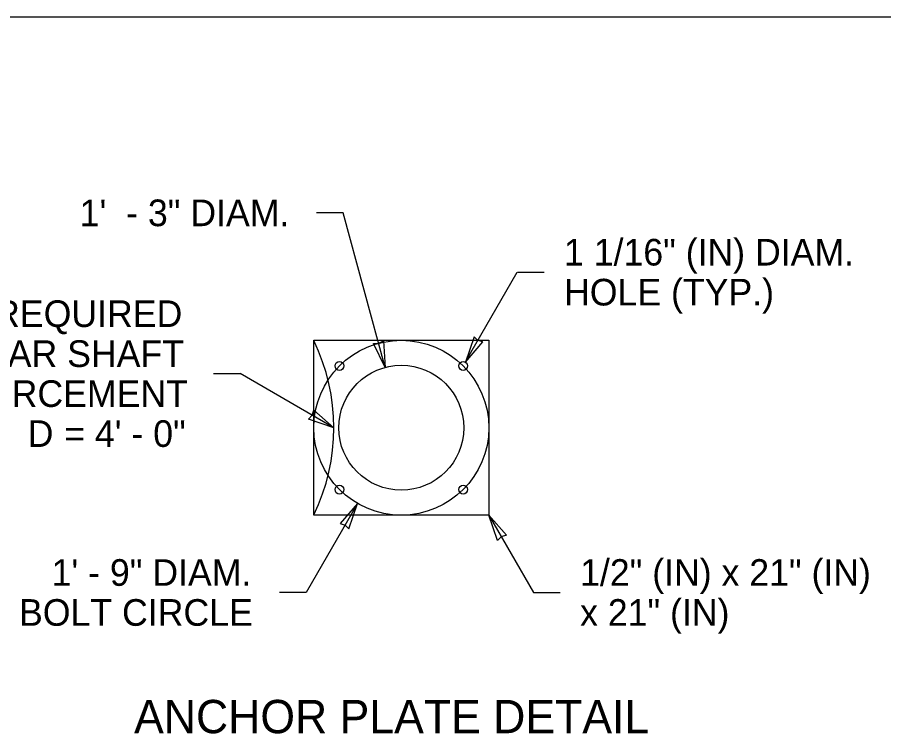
# Model space of a CAD drawing. Extents: x 99862 to 103151, y 100000 to 102076.
# Drawn here: x 102253 to 102772, y 101645 to 102075 of the extents above; entities that cross this region are included whole.
import ezdxf

# ---------------------------------------------------------------- set-up
doc = ezdxf.new("R2010")
doc.units = 0
for name, color, linetype in [('Level 15', 7, 'Continuous'), ('Level 20', 7, 'Continuous'), ('Level 23', 7, 'Continuous'), ('Level 60', 7, 'Continuous')]:
    doc.layers.add(name, color=color, linetype=linetype)

msp = doc.modelspace()

# ---------------------------------------------------------------- linework, layer by layer
at = {"layer": 'Level 15'}
for p, q in [((102448.18, 101957.6), (102432.18, 101957.6)), ((102448.18, 101957.6), (102432.18, 101957.6)), ((102473.22, 101864.77), (102448.18, 101957.6)), ((102521.71, 101868.45), (102552.61, 101921.98)), ((102552.62, 101921.98), (102568.62, 101921.98)), ((102552.62, 101921.98), (102568.62, 101921.98)), ((102370.2, 101861.06), (102386.2, 101861.06)), ((102370.2, 101861.06), (102386.2, 101861.06)), ((102442.49, 101828.56), (102386.2, 101861.06)), ((102456.74, 101783.1), (102425.89, 101729.66)), ((102535.49, 101776.06), (102562.28, 101729.66)), ((102425.89, 101729.66), (102409.89, 101729.66)), ((102425.89, 101729.66), (102409.89, 101729.66)), ((102562.28, 101729.66), (102578.28, 101729.66)), ((102562.28, 101729.66), (102578.28, 101729.66))]:
    msp.add_line(p, q, dxfattribs=at)
for points in [[(102521.44, 101867.99), (102531.98, 101880.06), (102528.94, 101880.97), (102526.63, 101883.15)], [(102473.22, 101864.77), (102466.25, 101879.19), (102469.41, 101879.27), (102472.21, 101880.76)], [(102442.49, 101828.56), (102427.33, 101833.75), (102429.5, 101836.06), (102430.41, 101839.1)], [(102456.74, 101783.1), (102446.21, 101771.02), (102449.24, 101770.11), (102451.55, 101767.94)], [(102456.74, 101783.1), (102446.21, 101771.02), (102449.24, 101770.11), (102451.55, 101767.94)], [(102535.49, 101776.06), (102546.02, 101763.99), (102542.99, 101763.08), (102540.68, 101760.9)]]:
    msp.add_lwpolyline(points, close=True, dxfattribs=at)
msp.add_circle((102482.99, 101828.56), 52.5, dxfattribs=at)
at = {"layer": 'Level 23'}
for p, q in [((102430.49, 101881.06), (102535.49, 101881.06)), ((102430.49, 101776.06), (102430.49, 101881.06)), ((102535.49, 101881.06), (102535.49, 101776.06)), ((102535.49, 101776.06), (102430.49, 101776.06))]:
    msp.add_line(p, q, dxfattribs=at)
for centre, radius in [((102445.87, 101865.69), 2.66), ((102445.87, 101865.69), 2.66), ((102482.99, 101828.56), 37.5), ((102520.11, 101865.69), 2.66), ((102520.11, 101865.69), 2.66), ((102445.87, 101791.44), 2.66), ((102445.87, 101791.44), 2.66), ((102520.11, 101791.44), 2.66), ((102520.11, 101791.44), 2.66)]:
    msp.add_circle(centre, radius, dxfattribs=at)
msp.add_arc((102322.49, 101828.56), 120, 334.1581, 25.8419, dxfattribs=at)
at = {"layer": 'Level 60'}
msp.add_line((103150, 102075), (100000, 102075), dxfattribs=at)

# ---------------------------------------------------------------- texts
at = {"layer": 'Level 20'}
for s, height, p in [('1\'  - 3" DIAM.', 16, (102290.01, 101949.6)), ('1 1/16" (IN) DIAM.', 16, (102580.62, 101925.98)), ('HOLE (TYP.)', 16, (102580.62, 101901.98)), ('NOTCH AS REQUIRED', 16, (102122.16, 101889.06)), ('TO CLEAR SHAFT', 16, (102169.54, 101865.06)), ('REINFORCEMENT', 16, (102168.34, 101841.06)), ('D', 16, (102258.79, 101817.06)), ('= 4\' - 0"', 16, (102280.69, 101817.06)), ('1\' - 9" DIAM.', 16, (102273.15, 101733.66)), ('1/2" (IN) x 21" (IN)', 16, (102590.28, 101733.66)), ('BOLT CIRCLE', 16, (102253.59, 101709.66)), ('x 21" (IN)', 16, (102590.28, 101709.66)), ('ANCHOR PLATE DETAIL', 20, (102322.63, 101645.16))]:
    msp.add_text(s, height=height, dxfattribs=at).set_placement(p)

doc.saveas('drawing.dxf')
